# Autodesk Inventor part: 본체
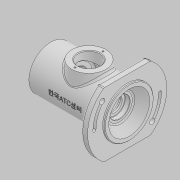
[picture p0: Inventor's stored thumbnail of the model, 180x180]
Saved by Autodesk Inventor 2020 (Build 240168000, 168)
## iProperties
Created: 2022-05
Part Number: 본체
Material: 일반
Document SubType Name: Modeling
Designer: User
Density: 1 g/cm^3
Appearance: 기본값
Author: User
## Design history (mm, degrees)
sketch "스케치1"
  geometry: L1 (0, 0)-(115, 0); L2 (115, 0)-(115, 36); L3 (115, 36)-(112, 36); L4 (112, 36)-(112, 58); L5 (112, 58)-(102, 58); L6 (102, 58)-(102, 32); L7 (102, 32)-(0, 32); L8 (0, 32)-(0, 0); L9 (11, 22.5)-(22, 22.5); L10 (22, 22.5)-(22, 17.5); L11 (22, 17.5)-(24.25, 17.5); L12 (24.25, 17.5)-(24.25, 18.5); L13 (24.25, 18.5)-(26, 18.5); L14 (26, 18.5)-(26, 17.5); L15 (26, 17.5)-(37, 17.5); L16 (37, 17.5)-(37, 27); L17 (75, 27)-(75, 17.5); L18 (75, 17.5)-(86, 17.5); L19 (86, 17.5)-(86, 15); L20 (86, 15)-(91, 15); L21 (91, 15)-(91, 11); L22 (91, 11)-(93.7, 11); L23 (93.7, 11)-(93.7, 15); L24 (101, 20)-(115, 30); L25 (93.7, 15)-(101, 15); L26 (101, 15)-(101, 20); L27 (37, 27)-(75, 27); L28 (11, 22.5)-(11, 24); L29 (11, 24)-(8, 24); L30 (8, 24)-(8, 22.5); L31 (8, 22.5)-(0, 22.5)
  constraints: 62 end point, 21 perpendicular, 4 horizontal, 2 point on line, 1 parallel, 1 vertical
  dimensions: "d0" = 115 distance of L1.start L1.end; "d1" = 72 diameter of L3 L1; "d2" = 116 diameter of L5 L1; "d3" = 64 diameter of L7 L1; "d4" = 13 distance between parallel lines of L6 L2; "d5" = 3 distance of L2.end L3.end; "d6" = 60 diameter of L24.end L1; "d7" = 40 diameter of L24.start L1; "d8" = 14 horizontal distance of L24.end L24.start; "d9" = 30 diameter of L25 L1; "d10" = 22 diameter of L22 L1; "d11" = 30 diameter of L20 L1; "d12" = 35 diameter of L18 L1; "d13" = 54 diameter of L27 L1; "d14" = 35 diameter of L15 L1; "d15" = 37 diameter of L13 L1; "d16" = 35 diameter of L11 L1; "d17" = 45 diameter of L9 L1; "d18" = 48 diameter of L29 L1; "d19" = 45 diameter of L31 L1; "d20" = 8 distance of L30.end L31.end; "d21" = 22 distance between parallel lines of L10 L8; "d22" = 3 distance of L28.end L29.end; "d23" = 29 distance between parallel lines of L19 L2; "d24" = 5 distance of L19.end L20.end; "d25" = 11 distance of L17.end L18.end; "d26" = 38 distance of L16.end L17.start; "d27" = 11 distance of L14.end L15.end; "d29" = 7.3 distance of L23.end L25.end; "d96" = 1.75 distance of L12.end L13.end
revolve "회전1" sketch "스케치1" stored, may be unused: angle "d30" = 90 deg
sketch "스케치2"
  geometry: L1 (-58, 47)-(58, 47); L2 (58, 47)-(58, -47); L3 (58, -47)-(-58, -47); L4 (-58, -47)-(-58, 47); A1 r 58 centre (0, 0) between (-58, 0) and (58, 0) reference; 5 further points
  constraints: 8 end point, 2 midpoint, 2 parallel, 2 point on circle, 1 horizontal, 1 horizontal alignment, 1 perpendicular
  dimensions: "d31" = 94 distance of L1.end L2.end
extrude "돌출1" cut sketch "스케치2" extent not by distance; stored distance "d32" = 0; taper "d33" = 0 deg
node "작업 평면1"
sketch "스케치3"
  geometry: C1 r 25 at (-56, 0); 1 further point
  constraints: 1 centre point, 1 horizontal alignment
  dimensions: "d35" = 50 diameter of C1; "d36" = 56 distance of C1.centre point (0, 0)
extrude "돌출2" join sketch "스케치3" stored distance "d37" = 10; taper "d38" = 5 deg
sketch "스케치4"
  geometry: C1 r 25 at (0, 0) reference; 2 further points
  constraints: 1 coincident
hole "구멍1" sketch "스케치4" at (0, 0) diameter "d39" = 32; stored, may be unused: countersink angle "d43" = 90 deg, drill point angle "d45" = 118 deg; dims "d40" = 6, "d41" = 4, "d42" = 2, "d44" = 8
sketch "스케치5"
  geometry: L1 (-48, 0)-(48, 0); L2 (-36.77, -30.854)-(36.77, 30.854); A1 r 48 centre (0, 0) between (48, 0) and (36.77, 30.854); A2 r 48 centre (0, 0) between (48, 0) and (36.77, 30.854); A3 r 52 centre (0, 0) between (52, 0) and (39.834, 33.425); A4 r 44 centre (0, 0) between (44, 0) and (33.706, 28.283); A5 r 4 centre (48, 0) between (44, 0) and (52, 0); A6 r 4 centre (36.77, 30.854) between (39.834, 33.425) and (33.706, 28.283); A7 r 50.25 centre (0, 0) between (50.25, 0) and (38.494, 32.3); A8 r 2.25 centre (48, 0) between (45.75, 0) and (50.25, 0); A9 r 45.75 centre (0, 0) between (45.75, 0) and (35.047, 29.408); A10 r 2.25 centre (36.77, 30.854) between (38.494, 32.3) and (35.047, 29.408); A11 r 48 centre (0, 0) between (-48, 0) and (-36.77, -30.854); A12 r 52 centre (0, 0) between (-52, 0) and (-39.834, -33.425); A13 r 44 centre (0, 0) between (-44, 0) and (-33.706, -28.283); A14 r 4 centre (-48, 0) between (-44, 0) and (-52, 0); A15 r 4 centre (-36.77, -30.854) between (-39.834, -33.425) and (-33.706, -28.283); A16 r 45.75 centre (0, 0) between (-45.75, 0) and (-35.047, -29.408); A17 r 2.25 centre (-48, 0) between (-45.75, 0) and (-50.25, 0); A18 r 50.25 centre (0, 0) between (-50.25, 0) and (-38.494, -32.3); A19 r 2.25 centre (-36.77, -30.854) between (-38.494, -32.3) and (-35.047, -29.408); 3 further points
  constraints: 40 point on circle, 19 centre point, 8 tangent, 5 coincident, 4 end point, 2 midpoint, 1 horizontal, 6 other
  dimensions: "d47" = 96 diameter of A1; "d48" = 40 deg angle of L2 L1; "d50" = 4 radius of A5; "d52" = 4.5 diameter of A8; "d53" = 4 radius of A15; "d54" = 4.5 diameter of A19
extrude "돌출3" cut sketch "스케치5" distance "d55" = 4.4; taper "d56" = 0 deg
extrude "돌출4" cut sketch "스케치5" extent not by distance; stored distance "d57" = 0; taper "d58" = 0 deg
hole "구멍2" sketch "스케치5" diameter "d59" = 8; stored, may be unused: countersink angle "d63" = 90 deg, drill point angle "d65" = 118 deg; dims "d60" = 6, "d61" = 4, "d62" = 2, "d64" = 8
sketch "스케치6" dims "d66" = 41
  geometry: L1 (0, 0)-(0, 20.5); C1 r 25 at (0, 0) reference; 2 further points
  constraints: 2 coincident, 2 end point, 1 vertical, 1 vertical alignment, 2 other
hole "구멍3" sketch "스케치6" at (0, 20.5) diameter "d67" = 2.62111; stored, may be unused: countersink angle "d71" = 90 deg, drill point angle "d73" = 118 deg; dims "d68" = 6, "d69" = 4, "d70" = 2, "d72" = 8
node "작업 평면2"
sketch "스케치7"
  geometry: L1 (64, -36)-(64, 36) reference; 2 further points
  constraints: 1 horizontal alignment, 1 other
  dimensions: "d77" = 62 distance from line of point (2, 0) L1
feature "엠보싱1" sketch "스케치7" dims "d78" = 0.5, "d79" = 0
chamfer "모따기1" distance "d80" = 0.7; stored, may be unused: second distance "d81" = 2, angle "d82" = 30 deg
chamfer "모따기2" distance "d83" = 1; stored, may be unused: second distance "d84" = 2, angle "d85" = 30 deg
fillet "모깎기1" dims "d86" = 0.5, "d87" = 0.6
fillet "모깎기2" dims "d88" = 3
feature "스레드1" dims "d89" = 8, "d90" = 0
fillet "모깎기3" dims "d91" = 3
chamfer "모따기3" distance "d92" = 1; stored, may be unused: second distance "d93" = 2, angle "d94" = 30 deg
fillet "모깎기4" dims "d95" = 3
node "솔리드1"
pattern_circular "원형 패턴1" dims angle "d75" = 360 deg
feature "A9D066F2-1C7D-4E18-AEED-F7BC21143FA4" dims "d89" = 8, "d90" = 0
other parameters: "d34" = 38
